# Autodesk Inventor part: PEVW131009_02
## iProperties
Created: 2009-10
Part Number: PEVW131009_02
Cost Center: 0 kg
Material: 1.0037 St 37-2
Document SubType Name: Blech
Designer: Student_TAB
Authority: 0 mm^3
Density: 7.85 g/cm^3
Author: Student_TAB
SaveDate: 2007-07-03
SaveTime: 10:26
TotalMass: 0 kg
TotalVolume: 0 mm^3
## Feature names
1. Abgeleiteter Körper1 [Tagging]
